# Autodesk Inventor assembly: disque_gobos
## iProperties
Created: 2011-01
Part Number: disque_gobos
Document SubType Name: Assembly
Designer: eric
Mass: 9.04256 g
Surface Area: 178.93 cm^2
Volume: 9.04256 cm^3
Density: 1 g/cm^3
Norme de conversion: IGES 5.3
Nom du fichier: No Iges File Name specified
Préprocesseur: Autodesk Inventor 2011
Postprocesseur: Build: 342, Release: 2008 SP3 - Date: Tue 05/27/2008
Unités envoyées: MM
Incertitude: 0.01
Author: eric
